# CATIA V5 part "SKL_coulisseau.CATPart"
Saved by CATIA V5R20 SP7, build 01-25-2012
Part number: SKL_coulisseau
Publications: "Droite.1", "Esquisse.1"
Bounding box of the stored display mesh (mm): x 0 to 0, y -50 to 100, z 0 to 31.823
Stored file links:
  F:\IAO_placube\SKL_coulisseau.CATPart
  F:\IAO_placube\Product1.CATProduct
  F:\IAO_placube\SKL_bati.CATPart
  F:\IAO_placube\SKL_general.CATPart
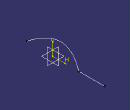
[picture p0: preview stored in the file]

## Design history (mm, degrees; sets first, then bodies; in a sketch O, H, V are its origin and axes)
Set1
  Point1: linked copy from another document
  Line1: linked copy from another document
  Plane1 "plan_ref": linked copy from another document
Body1 (main body)
  Line2: type PtDir, RefPoint Point1, Direction Line1, Start 0, End 50
  Sketch1 on Plane1, origin (0, 0, 0), H (0, 1, 0), V (0, 0, 1)
    spline S1 through (-50, 0) (40, 20) (50, 0)
    reference projected point E1 (50, 0) from vertex of Line2
    point P1 (-50, 0)
    point P2 (50, 0)
    coincidence: P1 H, P2 E1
